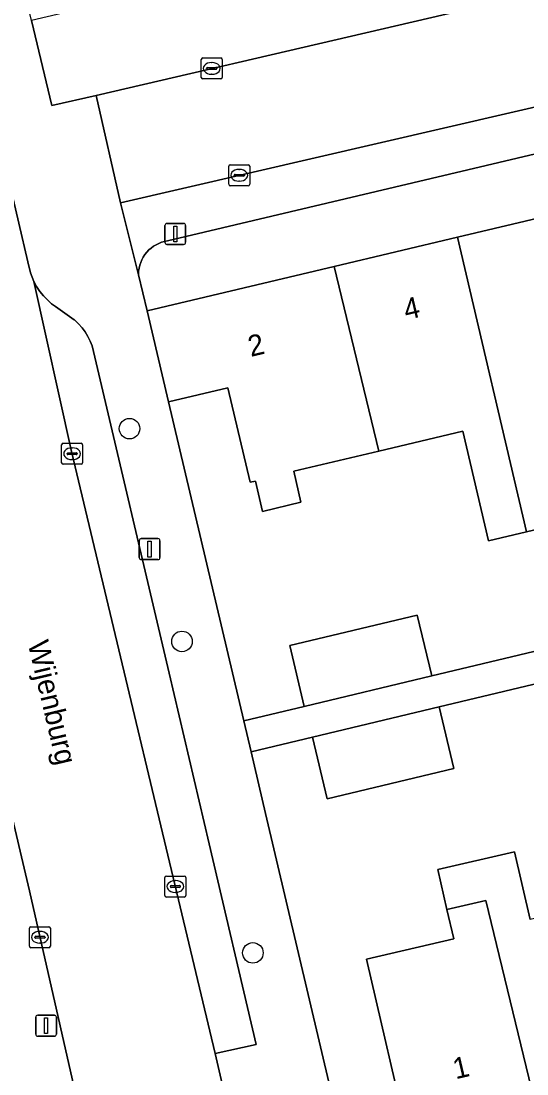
# Model space of a CAD drawing. Extents: x 158031 to 159244, y 380104 to 381214.
# Drawn here: x 158599.9 to 158624, y 380796.3 to 380846.4 of the extents above; entities that cross this region are included whole.
import ezdxf

# ---------------------------------------------------------------- set-up
doc = ezdxf.new("R2010")
doc.units = 0
for name, color, linetype in [('IMGEO_Boom', 7, 'Continuous'), ('IMGEO_Erf', 7, 'Continuous'), ('IMGEO_Kolk', 7, 'Continuous'), ('IMGEO_Lichtmast', 7, 'Continuous'), ('IMGEO_Muur', 7, 'Continuous'), ('IMGEO_Openbare_ruimte_label', 7, 'Continuous'), ('IMGEO_Pand', 7, 'Continuous'), ('IMGEO_Pand_nummerreeks', 7, 'Continuous'), ('IMGEO_Parkeervlak_open', 7, 'Continuous'), ('IMGEO_Rijbaan_lokaal_open', 7, 'Continuous'), ('IMGEO_Voetpad_open', 7, 'Continuous')]:
    doc.layers.add(name, color=color, linetype=linetype)

msp = doc.modelspace()

# ---------------------------------------------------------------- linework, layer by layer
at = {"layer": 'IMGEO_Boom'}
for centre in [(158605.056, 380826.997), (158607.553, 380816.873), (158610.928, 380802.058)]:
    msp.add_circle(centre, 0.489, dxfattribs=at)
at = {"layer": 'IMGEO_Erf'}
for points in [[(158649.472, 380846.005), (158606.862, 380835.923), (158606.722, 380835.897), (158606.584, 380835.859), (158606.45, 380835.808), (158606.322, 380835.746), (158606.2, 380835.672), (158606.084, 380835.588), (158605.977, 380835.494), (158605.878, 380835.391), (158605.789, 380835.279), (158605.711, 380835.16), (158605.643, 380835.034), (158605.587, 380834.903), (158605.543, 380834.767), (158605.511, 380834.628), (158605.491, 380834.486), (158605.485, 380834.344), (158605.485, 380834.31), (158605.888, 380832.607), (158614.795, 380834.714), (158620.666, 380836.102), (158626.506, 380837.484)], [(158625.69, 380822.495), (158623.945, 380822.082), (158622.146, 380821.657), (158620.913, 380826.87), (158616.918, 380825.925), (158612.869, 380824.967), (158613.217, 380823.495), (158611.386, 380823.062), (158611.045, 380824.504), (158610.798, 380824.446), (158609.734, 380828.944), (158606.913, 380828.277), (158610.493, 380813.095), (158613.371, 380813.782), (158612.681, 380816.674), (158618.749, 380818.122), (158619.439, 380815.23), (158654.76, 380823.659)], [(158656.575, 380822.533), (158619.79, 380813.755), (158620.489, 380810.827), (158614.467, 380809.39), (158613.768, 380812.318), (158610.841, 380811.62), (158611.532, 380808.69), (158615.134, 380793.418)], [(158624.83, 380792.91), (158622.619, 380792.398), (158622.285, 380793.841), (158618.374, 380792.936), (158616.332, 380801.759), (158620.489, 380802.721), (158620.165, 380804.12), (158619.725, 380806.022), (158623.374, 380806.866), (158624.117, 380803.653)]]:
    msp.add_lwpolyline(points, dxfattribs=at)
at = {"layer": 'IMGEO_Kolk'}
for p, q in [((158608.468, 380843.705), (158608.468, 380844.557)), ((158608.543, 380844.631), (158609.395, 380844.631)), ((158608.956, 380844.411), (158608.981, 380844.411)), ((158609.469, 380844.557), (158609.469, 380843.705)), ((158608.727, 380844.125), (158608.727, 380844.137)), ((158609.165, 380844.088), (158608.767, 380844.088)), ((158608.77, 380844.174), (158609.168, 380844.174)), ((158608.979, 380843.851), (158608.954, 380843.851)), ((158609.211, 380844.137), (158609.211, 380844.125)), ((158609.395, 380843.631), (158608.543, 380843.631)), ((158609.778, 380838.622), (158609.778, 380839.474)), ((158609.853, 380839.548), (158610.705, 380839.548)), ((158610.266, 380839.328), (158610.291, 380839.328)), ((158610.779, 380839.474), (158610.779, 380838.622)), ((158610.037, 380839.042), (158610.037, 380839.054)), ((158610.475, 380839.005), (158610.077, 380839.005)), ((158610.08, 380839.091), (158610.478, 380839.091)), ((158610.289, 380838.768), (158610.264, 380838.768)), ((158610.521, 380839.054), (158610.521, 380839.042)), ((158610.705, 380838.548), (158609.853, 380838.548)), ((158601.824, 380825.377), (158601.824, 380826.229)), ((158601.899, 380826.303), (158602.751, 380826.303)), ((158602.825, 380826.229), (158602.825, 380825.377)), ((158602.083, 380825.797), (158602.083, 380825.809)), ((158602.521, 380825.76), (158602.123, 380825.76)), ((158602.126, 380825.846), (158602.524, 380825.846)), ((158602.312, 380826.083), (158602.337, 380826.083)), ((158602.567, 380825.809), (158602.567, 380825.797)), ((158602.751, 380825.303), (158601.899, 380825.303)), ((158602.335, 380825.523), (158602.31, 380825.523)), ((158606.811, 380805.715), (158607.663, 380805.715)), ((158606.736, 380804.789), (158606.736, 380805.641)), ((158606.995, 380805.209), (158606.995, 380805.221)), ((158607.433, 380805.172), (158607.035, 380805.172)), ((158607.038, 380805.258), (158607.436, 380805.258)), ((158607.224, 380805.495), (158607.249, 380805.495)), ((158607.479, 380805.221), (158607.479, 380805.209)), ((158607.737, 380805.641), (158607.737, 380804.789)), ((158607.663, 380804.715), (158606.811, 380804.715)), ((158607.247, 380804.935), (158607.222, 380804.935)), ((158600.291, 380802.377), (158600.291, 380803.229)), ((158600.366, 380803.303), (158601.218, 380803.303)), ((158601.292, 380803.229), (158601.292, 380802.377)), ((158600.55, 380802.797), (158600.55, 380802.809)), ((158600.988, 380802.76), (158600.59, 380802.76)), ((158600.593, 380802.846), (158600.991, 380802.846)), ((158600.779, 380803.083), (158600.804, 380803.083)), ((158601.034, 380802.809), (158601.034, 380802.797)), ((158601.218, 380802.303), (158600.366, 380802.303)), ((158600.802, 380802.523), (158600.777, 380802.523))]:
    msp.add_line(p, q, dxfattribs=at)
for points in [[(158608.468, 380843.705), (158608.468, 380844.557)], [(158608.543, 380844.631), (158609.395, 380844.631)], [(158609.469, 380844.557), (158609.469, 380843.705)], [(158609.395, 380843.631), (158608.543, 380843.631)], [(158609.778, 380838.622), (158609.778, 380839.474)], [(158609.853, 380839.548), (158610.705, 380839.548)], [(158610.779, 380839.474), (158610.779, 380838.622)], [(158610.705, 380838.548), (158609.853, 380838.548)], [(158601.824, 380825.377), (158601.824, 380826.229)], [(158601.899, 380826.303), (158602.751, 380826.303)], [(158602.825, 380826.229), (158602.825, 380825.377)], [(158602.751, 380825.303), (158601.899, 380825.303)], [(158606.811, 380805.715), (158607.663, 380805.715)], [(158606.736, 380804.789), (158606.736, 380805.641)], [(158607.737, 380805.641), (158607.737, 380804.789)], [(158607.663, 380804.715), (158606.811, 380804.715)], [(158600.291, 380802.377), (158600.291, 380803.229)], [(158600.366, 380803.303), (158601.218, 380803.303)], [(158601.292, 380803.229), (158601.292, 380802.377)], [(158601.218, 380802.303), (158600.366, 380802.303)]]:
    msp.add_lwpolyline(points, dxfattribs=at)
for centre, radius, start, end in [((158608.545, 380844.555), 0.0765, 91.552, 178.448), ((158608.545, 380844.555), 0.0765, 91.552, 178.448), ((158609.393, 380844.555), 0.0765, 1.552, 88.448), ((158609.393, 380844.555), 0.0765, 1.552, 88.448), ((158608.767, 380844.134), 0.0403, 85.8775, 175.7526), ((158608.764, 380844.124), 0.0366, 178.938, 274.7102), ((158609.168, 380844.131), 0.043, 264.8664, 352.4533), ((158609.172, 380844.136), 0.0386, 1.7309, 96.639), ((158608.545, 380843.707), 0.0765, 181.552, 268.448), ((158608.545, 380843.707), 0.0765, 181.552, 268.448), ((158609.393, 380843.707), 0.0765, 271.552, 358.448), ((158609.393, 380843.707), 0.0765, 271.552, 358.448), ((158609.855, 380839.472), 0.0765, 91.552, 178.448), ((158609.855, 380839.472), 0.0765, 91.552, 178.448), ((158610.703, 380839.472), 0.0765, 1.552, 88.448), ((158610.703, 380839.472), 0.0765, 1.552, 88.448), ((158610.077, 380839.051), 0.0403, 85.8775, 175.7526), ((158610.074, 380839.041), 0.0366, 178.938, 274.7102), ((158610.478, 380839.048), 0.043, 264.8664, 352.4533), ((158610.482, 380839.053), 0.0386, 1.7309, 96.639), ((158609.855, 380838.624), 0.0765, 181.552, 268.448), ((158609.855, 380838.624), 0.0765, 181.552, 268.448), ((158610.703, 380838.624), 0.0765, 271.552, 358.448), ((158610.703, 380838.624), 0.0765, 271.552, 358.448), ((158601.901, 380826.227), 0.0765, 91.552, 178.448), ((158601.901, 380826.227), 0.0765, 91.552, 178.448), ((158602.749, 380826.227), 0.0765, 1.552, 88.448), ((158602.749, 380826.227), 0.0765, 1.552, 88.448), ((158602.123, 380825.806), 0.0403, 85.8775, 175.7526), ((158602.12, 380825.796), 0.0366, 178.938, 274.7102), ((158602.524, 380825.803), 0.043, 264.8664, 352.4533), ((158602.528, 380825.808), 0.0386, 1.7309, 96.639), ((158601.901, 380825.379), 0.0765, 181.552, 268.448), ((158601.901, 380825.379), 0.0765, 181.552, 268.448), ((158602.749, 380825.379), 0.0765, 271.552, 358.448), ((158602.749, 380825.379), 0.0765, 271.552, 358.448), ((158606.813, 380805.639), 0.0765, 91.552, 178.448), ((158606.813, 380805.639), 0.0765, 91.552, 178.448), ((158607.661, 380805.639), 0.0765, 1.552, 88.448), ((158607.661, 380805.639), 0.0765, 1.552, 88.448), ((158607.035, 380805.218), 0.0403, 85.8775, 175.7526), ((158607.032, 380805.208), 0.0366, 178.938, 274.7102), ((158607.436, 380805.215), 0.043, 264.8664, 352.4533), ((158607.44, 380805.22), 0.0386, 1.7309, 96.639), ((158606.813, 380804.791), 0.0765, 181.552, 268.448), ((158606.813, 380804.791), 0.0765, 181.552, 268.448), ((158607.661, 380804.791), 0.0765, 271.552, 358.448), ((158607.661, 380804.791), 0.0765, 271.552, 358.448), ((158600.368, 380803.227), 0.0765, 91.552, 178.448), ((158600.368, 380803.227), 0.0765, 91.552, 178.448), ((158601.216, 380803.227), 0.0765, 1.552, 88.448), ((158601.216, 380803.227), 0.0765, 1.552, 88.448), ((158600.59, 380802.806), 0.0403, 85.8775, 175.7526), ((158600.587, 380802.796), 0.0366, 178.938, 274.7102), ((158600.991, 380802.803), 0.043, 264.8664, 352.4533), ((158600.995, 380802.808), 0.0386, 1.7309, 96.639), ((158600.368, 380802.379), 0.0765, 181.552, 268.448), ((158600.368, 380802.379), 0.0765, 181.552, 268.448), ((158601.216, 380802.379), 0.0765, 271.552, 358.448), ((158601.216, 380802.379), 0.0765, 271.552, 358.448)]:
    msp.add_arc(centre, radius, start, end, dxfattribs=at)
for centre, major_axis, ratio, start_param, end_param in [((158608.955, 380844.131), (-0.387, 0.002), 0.722429, 4.712389, 7.853982), ((158608.98, 380844.131), (-0.39, 0.002), 0.717154, 1.570796, 4.712389), ((158610.265, 380839.048), (-0.387, 0.002), 0.722429, 4.712389, 7.853982), ((158610.29, 380839.048), (-0.39, 0.002), 0.717154, 1.570796, 4.712389), ((158602.311, 380825.803), (-0.387, 0.002), 0.722429, 4.712389, 7.853982), ((158602.336, 380825.803), (-0.39, 0.002), 0.717154, 1.570796, 4.712389), ((158607.223, 380805.215), (-0.387, 0.002), 0.722429, 4.712389, 7.853982), ((158607.248, 380805.215), (-0.39, 0.002), 0.717154, 1.570796, 4.712389), ((158600.778, 380802.803), (-0.387, 0.002), 0.722429, 4.712389, 7.853982), ((158600.803, 380802.803), (-0.39, 0.002), 0.717154, 1.570796, 4.712389)]:
    msp.add_ellipse(centre, major_axis=major_axis, ratio=ratio, start_param=start_param, end_param=end_param, dxfattribs=at)
at = {"layer": 'IMGEO_Lichtmast'}
for p, q in [((158606.837, 380836.76), (158607.627, 380836.76)), ((158607.627, 380836.76), (158606.837, 380836.76)), ((158606.737, 380835.86), (158606.737, 380836.66)), ((158606.737, 380836.66), (158606.737, 380835.86)), ((158607.727, 380836.66), (158607.727, 380835.86)), ((158607.727, 380835.86), (158607.727, 380836.66)), ((158607.627, 380835.76), (158606.837, 380835.76)), ((158606.837, 380835.76), (158607.627, 380835.76)), ((158605.615, 380821.765), (158606.405, 380821.765)), ((158606.405, 380821.765), (158605.615, 380821.765)), ((158605.515, 380820.865), (158605.515, 380821.665)), ((158605.515, 380821.665), (158605.515, 380820.865)), ((158606.505, 380821.665), (158606.505, 380820.865)), ((158606.505, 380820.865), (158606.505, 380821.665)), ((158606.405, 380820.765), (158605.615, 380820.765)), ((158605.615, 380820.765), (158606.405, 380820.765)), ((158600.589, 380798.193), (158600.589, 380798.993)), ((158600.589, 380798.993), (158600.589, 380798.193)), ((158600.689, 380799.093), (158601.479, 380799.093)), ((158601.479, 380799.093), (158600.689, 380799.093)), ((158601.579, 380798.993), (158601.579, 380798.193)), ((158601.579, 380798.193), (158601.579, 380798.993)), ((158601.479, 380798.093), (158600.689, 380798.093)), ((158600.689, 380798.093), (158601.479, 380798.093))]:
    msp.add_line(p, q, dxfattribs=at)
for points in [[(158607.157, 380836.635), (158607.307, 380836.635), (158607.307, 380835.885), (158607.157, 380835.885), (158607.157, 380836.635)], [(158605.935, 380821.64), (158606.085, 380821.64), (158606.085, 380820.89), (158605.935, 380820.89), (158605.935, 380821.64)], [(158601.009, 380798.968), (158601.159, 380798.968), (158601.159, 380798.218), (158601.009, 380798.218), (158601.009, 380798.968)]]:
    msp.add_lwpolyline(points, dxfattribs=at)
for centre, start, end in [((158606.837, 380836.66), 90, 180), ((158606.837, 380836.66), 90, 180), ((158607.627, 380836.66), 0, 90), ((158607.627, 380836.66), 360, 90), ((158606.837, 380835.86), 180, 270), ((158606.837, 380835.86), 180, 270), ((158607.627, 380835.86), 270, 0), ((158607.627, 380835.86), 270, 0), ((158605.615, 380821.665), 90, 180), ((158605.615, 380821.665), 90, 180), ((158606.405, 380821.665), 0, 90), ((158606.405, 380821.665), 360, 90), ((158605.615, 380820.865), 180, 270), ((158605.615, 380820.865), 180, 270), ((158606.405, 380820.865), 270, 0), ((158606.405, 380820.865), 270, 0), ((158600.689, 380798.993), 90, 180), ((158600.689, 380798.993), 90, 180), ((158601.479, 380798.993), 0, 90), ((158601.479, 380798.993), 360, 90), ((158600.689, 380798.193), 180, 270), ((158600.689, 380798.193), 180, 270), ((158601.479, 380798.193), 270, 0), ((158601.479, 380798.193), 270, 0)]:
    msp.add_arc(centre, 0.1, start, end, dxfattribs=at)
at = {"layer": 'IMGEO_Muur'}
msp.add_lwpolyline([(158611.532, 380808.69), (158615.134, 380793.418)], dxfattribs=at)
at = {"layer": 'IMGEO_Pand'}
for points in [[(158623.945, 380822.082), (158625.69, 380822.495), (158624.437, 380827.789), (158628.571, 380828.767), (158626.506, 380837.484), (158620.666, 380836.102)], [(158623.945, 380822.082), (158620.666, 380836.102), (158614.795, 380834.714), (158616.918, 380825.925), (158620.913, 380826.87), (158622.146, 380821.657)], [(158614.795, 380834.714), (158605.888, 380832.607), (158606.913, 380828.277), (158609.734, 380828.944), (158610.798, 380824.446), (158611.045, 380824.504), (158611.386, 380823.062), (158613.217, 380823.495), (158612.869, 380824.967), (158616.918, 380825.925)], [(158613.371, 380813.782), (158619.439, 380815.23), (158618.749, 380818.122), (158612.681, 380816.674)], [(158614.467, 380809.39), (158620.489, 380810.827), (158619.79, 380813.755), (158613.768, 380812.318)], [(158628.154, 380804.587), (158624.117, 380803.653), (158623.374, 380806.866), (158619.725, 380806.022), (158620.165, 380804.12), (158622.011, 380804.547), (158624.83, 380792.91), (158627.002, 380793.413), (158626.667, 380794.861), (158630.279, 380795.697)], [(158624.83, 380792.91), (158622.011, 380804.547), (158620.165, 380804.12), (158620.489, 380802.721), (158616.332, 380801.759), (158618.374, 380792.936), (158622.285, 380793.841), (158622.619, 380792.398)]]:
    msp.add_lwpolyline(points, close=True, dxfattribs=at)
at = {"layer": 'IMGEO_Parkeervlak_open'}
for points in [[(158629.142, 380848.822), (158628.202, 380852.801), (158628.171, 380852.931), (158625.609, 380852.33), (158600.398, 380846.416), (158601.363, 380842.36), (158603.468, 380842.85)], [(158608.844, 380807.251), (158606.935, 380815.371), (158603.276, 380830.933), (158603.186, 380831.164), (158603.075, 380831.386), (158602.945, 380831.597), (158602.797, 380831.795), (158602.631, 380831.98), (158602.45, 380832.149), (158602.423, 380832.171), (158601.539, 380832.8), (158601.35, 380832.938), (158601.145, 380833.117), (158600.957, 380833.313), (158600.786, 380833.525), (158600.636, 380833.751), (158600.506, 380833.99), (158602.299, 380825.906), (158609.13, 380797.277), (158611.089, 380797.703)]]:
    msp.add_lwpolyline(points, close=True, dxfattribs=at)
at = {"layer": 'IMGEO_Rijbaan_lokaal_open'}
msp.add_lwpolyline([(158612.554, 380782.409), (158609.13, 380797.277), (158602.299, 380825.906), (158600.506, 380833.99), (158600.339, 380834.407), (158600.216, 380834.929), (158598.482, 380842.295), (158592.846, 380866.236), (158592.496, 380867.568), (158592.029, 380868.864), (158585.362, 380867.367), (158585.66, 380866.767), (158585.904, 380866.143), (158600.289, 380805.01), (158601.755, 380798.591), (158602.585, 380794.954)], dxfattribs=at)
msp.add_lwpolyline([(158694.977, 380856.819), (158694.506, 380858.735), (158693.674, 380862.117), (158693.184, 380864.068), (158690.982, 380863.5), (158663.759, 380857.034), (158634.489, 380850.082), (158629.142, 380848.822), (158603.468, 380842.85), (158604.621, 380837.745), (158632.417, 380844.154), (158677.296, 380854.712), (158677.726, 380852.891), (158684.625, 380823.643), (158679.739, 380822.539), (158683.037, 380808.743), (158686.584, 380809.65), (158689.75, 380828.266), (158701.345, 380831.114)], close=True, dxfattribs=at)
at = {"layer": 'IMGEO_Voetpad_open'}
for points in [[(158602.585, 380794.954), (158601.755, 380798.591), (158600.289, 380805.01), (158585.904, 380866.143), (158585.66, 380866.767), (158585.362, 380867.367), (158580.964, 380866.54), (158581.125, 380866.558), (158581.286, 380866.563), (158581.448, 380866.553), (158581.608, 380866.528), (158581.765, 380866.49), (158581.918, 380866.437), (158582.065, 380866.371), (158582.206, 380866.292), (158582.34, 380866.201), (158582.465, 380866.099), (158582.58, 380865.985), (158582.685, 380865.862), (158582.778, 380865.73), (158582.859, 380865.59), (158582.927, 380865.443), (158599.515, 380795.166)], [(158592.846, 380866.236), (158598.482, 380842.295), (158600.216, 380834.929), (158600.339, 380834.407), (158600.506, 380833.99), (158600.636, 380833.751), (158600.786, 380833.525), (158600.957, 380833.313), (158601.145, 380833.117), (158601.35, 380832.938), (158601.539, 380832.8), (158602.423, 380832.171), (158602.45, 380832.149), (158602.631, 380831.98), (158602.797, 380831.795), (158602.945, 380831.597), (158603.075, 380831.386), (158603.186, 380831.164), (158603.276, 380830.933), (158606.935, 380815.371), (158608.844, 380807.251), (158611.089, 380797.703), (158609.13, 380797.277), (158612.554, 380782.409)], [(158631.622, 380724.15), (158625.471, 380750), (158624.571, 380753.829), (158624.245, 380755.218), (158618.173, 380781.048), (158616.032, 380789.635), (158615.986, 380789.803), (158615.134, 380793.418), (158611.532, 380808.69), (158610.841, 380811.62), (158610.493, 380813.095), (158606.913, 380828.277), (158605.888, 380832.607), (158605.485, 380834.31), (158604.621, 380837.745), (158603.468, 380842.85), (158601.363, 380842.36), (158600.398, 380846.416), (158599.44, 380850.442), (158596.12, 380864.401)], [(158632.417, 380844.154), (158604.621, 380837.745), (158605.485, 380834.31), (158605.485, 380834.344), (158605.491, 380834.486), (158605.511, 380834.628), (158605.543, 380834.767), (158605.587, 380834.903), (158605.643, 380835.034), (158605.711, 380835.16), (158605.789, 380835.279), (158605.878, 380835.391), (158605.977, 380835.494), (158606.084, 380835.588), (158606.2, 380835.672), (158606.322, 380835.746), (158606.45, 380835.808), (158606.584, 380835.859), (158606.722, 380835.897), (158606.862, 380835.923), (158649.472, 380846.005)]]:
    msp.add_lwpolyline(points, dxfattribs=at)
msp.add_lwpolyline([(158655.594, 380826.799), (158655.185, 380828.559), (158652.827, 380838.378), (158651.393, 380844.44), (158650.941, 380846.353), (158649.472, 380846.005), (158650.164, 380843.079), (158651.315, 380838.214), (158652.218, 380834.399), (158654.76, 380823.659), (158619.439, 380815.23), (158613.371, 380813.782), (158610.493, 380813.095), (158610.841, 380811.62), (158613.768, 380812.318), (158619.79, 380813.755), (158656.575, 380822.533)], close=True, dxfattribs=at)

# ---------------------------------------------------------------- texts
at = {"layer": 'IMGEO_Openbare_ruimte_label'}
msp.add_text('Wijenburg', height=1, rotation=283.2996, dxfattribs=at).set_placement((158600.208, 380816.788))
at = {"layer": 'IMGEO_Pand_nummerreeks'}
for s, rotation, p in [('4', 13.3069, (158618.229, 380832.156)), ('2', 13.3069, (158610.827, 380830.405)), ('1', 13.209, (158620.577, 380796.041))]:
    msp.add_text(s, height=1, rotation=rotation, dxfattribs=at).set_placement(p)

doc.saveas('drawing.dxf')
